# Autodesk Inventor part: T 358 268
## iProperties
Created: 2006-03
Part Number: T 358 268
Material: 1.0718.07
Document SubType Name: Modeling
Designer: I.Baliuc
Description: Scheibe
Density: 7.84 g/cm^3
Title: Scheibe
Company: Mayer & Müller AG Schaltgeräte
HalbzeugNorm: DIN 671
Zweck: Druckplatte Trenner
Abmessung: Rd. 35
Author: T.Messerschmitt
Revision Number: 358268
Keywords: 266464
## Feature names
1. Extrusion2
